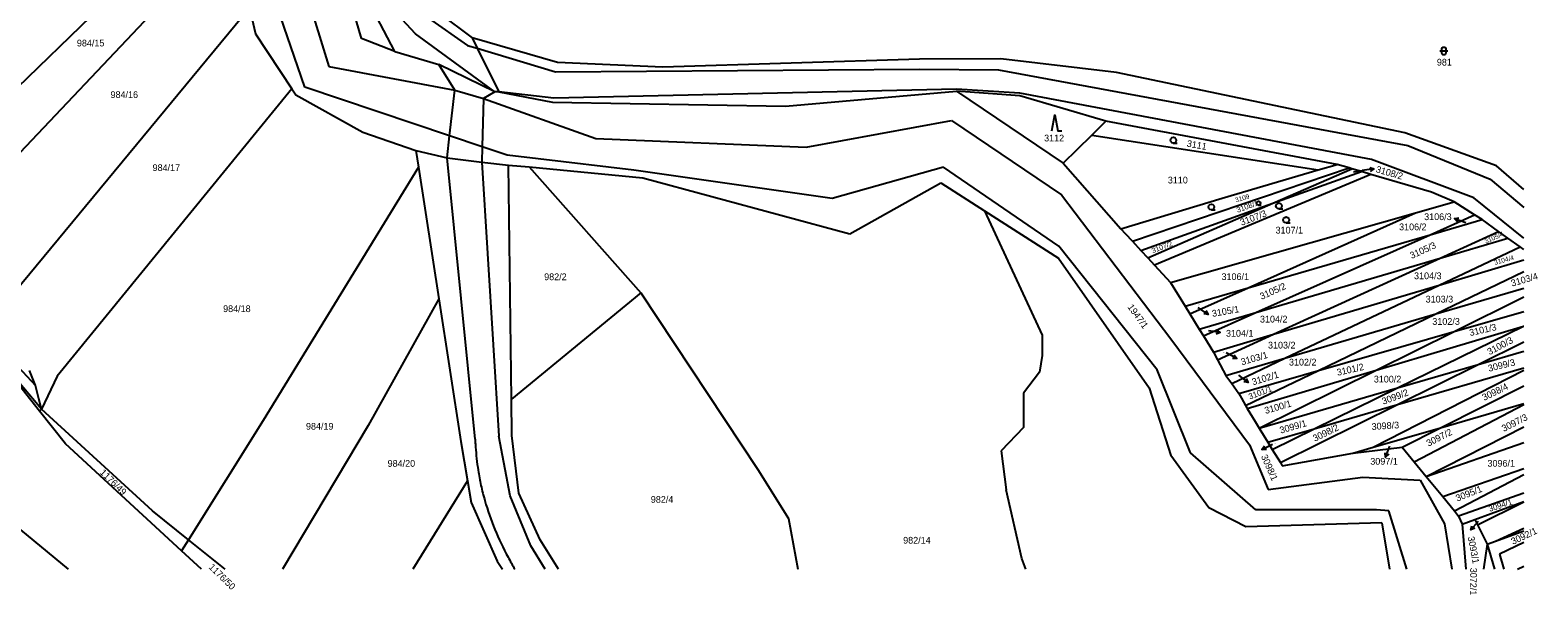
# Model space of a CAD drawing. Extents: x -621797 to -620972, y -1175539 to -1174697.
# Drawn here: x -621354.5 to -620973.6, y -1175539.3 to -1175396.7 of the extents above; entities that cross this region are included whole.
import ezdxf

# ---------------------------------------------------------------- set-up
doc = ezdxf.new("R2010")
doc.units = 0
for name, color, linetype in [('INZ mimo EON - nadz', 7, 'Continuous'), ('SDEL EON', 7, 'Continuous'), ('SDEL EON - popis', 7, 'Continuous'), ('Silnoproud EON', 7, 'Continuous'), ('Silnoproud EON - popis', 7, 'Continuous')]:
    doc.layers.add(name, color=color, linetype=linetype)

msp = doc.modelspace()

# ---------------------------------------------------------------- linework, layer by layer
at = {"layer": 'INZ mimo EON - nadz'}
for p, q in [((-621020.18, -1175432.47), (-621017.97, -1175432.16)), ((-621014.999, -1175431.743), (-621017.97, -1175432.16)), ((-620994.629, -1175444.275), (-620991.81, -1175445.3)), ((-621056.902, -1175468.48), (-621059.36, -1175466.76)), ((-621053.829, -1175473.097), (-621056.8, -1175472.68)), ((-621049.627, -1175479.602), (-621052.3, -1175478.24)), ((-621046.743, -1175485.685), (-621049.14, -1175483.88)), ((-621043.283, -1175502.592), (-621040.61, -1175501.23)), ((-621012.085, -1175504.531), (-621011.01, -1175501.73)), ((-620990.518, -1175522.934), (-620988.55, -1175520.67))]:
    msp.add_line(p, q, dxfattribs=at)
for points in [[(-621016.059, -1175431.387), (-621014.999, -1175431.743), (-621015.92, -1175432.377)], [(-620993.86, -1175445.086), (-620994.629, -1175444.275), (-620993.519, -1175444.147)], [(-621057.435, -1175467.497), (-621056.902, -1175468.48), (-621058.008, -1175468.316)], [(-621054.75, -1175472.463), (-621053.829, -1175473.097), (-621054.889, -1175473.453)], [(-621050.291, -1175478.703), (-621049.627, -1175479.602), (-621050.745, -1175479.594)], [(-621047.242, -1175484.684), (-621046.743, -1175485.685), (-621047.843, -1175485.482)], [(-621042.165, -1175502.583), (-621043.283, -1175502.592), (-621042.619, -1175501.692)], [(-621011.26, -1175503.776), (-621012.085, -1175504.531), (-621012.194, -1175503.418)], [(-620989.485, -1175522.507), (-620990.518, -1175522.934), (-620990.239, -1175521.851)]]:
    msp.add_lwpolyline(points, dxfattribs=at)
at = {"layer": 'SDEL EON'}
msp.add_lwpolyline([(-620997.82, -1175401.45), (-620997.72, -1175401.16), (-620997.47, -1175400.98), (-620997.16, -1175400.98), (-620996.91, -1175401.16), (-620996.81, -1175401.45), (-620996.81, -1175402.45), (-620996.91, -1175402.74), (-620997.16, -1175402.92), (-620997.47, -1175402.92), (-620997.72, -1175402.74), (-620997.82, -1175402.45)], close=True, dxfattribs=at)
for points in [[(-620998.32, -1175401.95), (-620997.05, -1175401.95), (-620996.32, -1175401.95)], [(-621096.38, -1175422.11), (-621095.63, -1175418.11), (-621094.88, -1175422.11), (-621093.88, -1175422.11)], [(-621065.66, -1175425.23), (-621066.04, -1175425.13), (-621066.31, -1175424.86), (-621066.41, -1175424.49), (-621066.31, -1175424.12), (-621066.04, -1175423.85), (-621065.67, -1175423.75), (-621065.3, -1175423.85), (-621065.03, -1175424.12), (-621064.93, -1175424.5), (-621065.03, -1175424.88), (-621065.3, -1175425.15), (-621065.68, -1175425.25), (-621064.68, -1175425.25)], [(-621056.05, -1175442.1), (-621056.43, -1175442), (-621056.7, -1175441.73), (-621056.8, -1175441.36), (-621056.7, -1175440.99), (-621056.43, -1175440.72), (-621056.06, -1175440.62), (-621055.69, -1175440.72), (-621055.42, -1175440.99), (-621055.32, -1175441.37), (-621055.42, -1175441.75), (-621055.69, -1175442.02), (-621056.07, -1175442.12), (-621055.07, -1175442.12)], [(-621044.13, -1175440.87), (-621044.385, -1175440.803), (-621044.566, -1175440.622), (-621044.632, -1175440.374), (-621044.566, -1175440.126), (-621044.385, -1175439.945), (-621044.137, -1175439.878), (-621043.889, -1175439.945), (-621043.708, -1175440.126), (-621043.641, -1175440.381), (-621043.708, -1175440.636), (-621043.889, -1175440.816), (-621044.143, -1175440.883), (-621043.473, -1175440.883)], [(-621038.99, -1175441.84), (-621039.37, -1175441.74), (-621039.64, -1175441.47), (-621039.74, -1175441.1), (-621039.64, -1175440.73), (-621039.37, -1175440.46), (-621039, -1175440.36), (-621038.63, -1175440.46), (-621038.36, -1175440.73), (-621038.26, -1175441.11), (-621038.36, -1175441.49), (-621038.63, -1175441.76), (-621039.01, -1175441.86), (-621038.01, -1175441.86)], [(-621037.16, -1175445.37), (-621037.54, -1175445.27), (-621037.81, -1175445), (-621037.91, -1175444.63), (-621037.81, -1175444.26), (-621037.54, -1175443.99), (-621037.17, -1175443.89), (-621036.8, -1175443.99), (-621036.53, -1175444.26), (-621036.43, -1175444.64), (-621036.53, -1175445.02), (-621036.8, -1175445.29), (-621037.18, -1175445.39), (-621036.18, -1175445.39)]]:
    msp.add_lwpolyline(points, dxfattribs=at)
at = {"layer": 'SDEL EON - popis'}
for p, q in [((-621292.93, -1175360.5), (-621279.04, -1175405.89)), ((-621285.12, -1175411.09), (-621299.97, -1175367.6)), ((-621257.16, -1175397.67), (-621270.32, -1175383.39)), ((-621253.83, -1175393.72), (-621243.98, -1175400.59)), ((-621237.07, -1175412.28), (-621257.16, -1175397.67)), ((-621243.98, -1175400.59), (-621241.51, -1175401.27)), ((-621241.51, -1175401.27), (-621221.72, -1175407.2)), ((-621247.23, -1175411.83), (-621251.26, -1175405.42)), ((-621279.04, -1175405.89), (-621247.23, -1175411.83)), ((-621221.72, -1175407.2), (-621129.8, -1175406.56)), ((-621129.8, -1175406.56), (-621109.82, -1175406.73)), ((-621109.82, -1175406.73), (-621006.47, -1175425.84)), ((-621248.5, -1175423.41), (-621285.12, -1175411.09)), ((-621248.5, -1175423.41), (-621247.23, -1175411.83)), ((-621247.23, -1175411.83), (-621239.98, -1175413.95)), ((-621237.07, -1175412.28), (-621239.98, -1175413.95)), ((-621222.14, -1175413.86), (-621236.04, -1175412.28)), ((-621120.48, -1175411.65), (-621222.14, -1175413.86)), ((-621104.47, -1175412.63), (-621120.48, -1175411.65)), ((-621015.6, -1175429.36), (-621104.47, -1175412.63)), ((-621239.98, -1175413.95), (-621240.29, -1175426.17)), ((-621239.98, -1175413.95), (-621211.57, -1175424.06)), ((-621158.44, -1175426.27), (-621121.73, -1175419.5)), ((-621121.73, -1175419.5), (-621093.92, -1175438.29)), ((-621249.11, -1175428.98), (-621248.5, -1175423.41)), ((-621240.29, -1175426.17), (-621248.5, -1175423.41)), ((-621211.57, -1175424.06), (-621158.44, -1175426.27)), ((-621240.29, -1175426.17), (-621240.39, -1175430.02)), ((-621233.98, -1175428.29), (-621240.29, -1175426.17)), ((-621226.14, -1175429.22), (-621233.98, -1175428.29)), ((-621006.47, -1175425.84), (-620985.63, -1175434.32)), ((-621242.06, -1175500.03), (-621249.11, -1175428.98)), ((-621240.39, -1175430.02), (-621236.06, -1175499.27)), ((-621201.98, -1175432.08), (-621226.14, -1175429.22)), ((-621151.88, -1175439.2), (-621201.98, -1175432.08)), ((-621123.75, -1175431.33), (-621151.88, -1175439.2)), ((-621094.57, -1175451.27), (-621123.75, -1175431.33)), ((-620989.75, -1175439.04), (-621015.6, -1175429.36)), ((-620985.63, -1175434.32), (-620977.15, -1175441.483)), ((-621093.92, -1175438.29), (-621066.32, -1175474.66)), ((-620977.15, -1175449.245), (-620989.75, -1175439.04)), ((-621069.73, -1175482.45), (-621094.57, -1175451.27)), ((-621066.32, -1175474.66), (-621046.47, -1175501.41)), ((-621061.34, -1175503.42), (-621069.73, -1175482.45)), ((-621233.25, -1175514.3), (-621236.06, -1175499.27)), ((-621044.82, -1175517.84), (-621061.34, -1175503.42)), ((-621046.47, -1175501.41), (-621041.73, -1175512.7)), ((-621041.73, -1175512.7), (-621017.8, -1175509.58)), ((-621017.8, -1175509.58), (-621003.35, -1175510.34)), ((-621003.35, -1175510.34), (-620997.17, -1175521.41)), ((-621228, -1175526.96), (-621233.25, -1175514.3)), ((-621014.32, -1175517.88), (-621044.82, -1175517.84)), ((-621011.23, -1175518.06), (-621014.32, -1175517.88)), ((-621006.711, -1175532.85), (-621011.23, -1175518.06)), ((-620997.17, -1175521.41), (-620995.336, -1175532.85)), ((-621224.335, -1175532.85), (-621228, -1175526.96))]:
    msp.add_line(p, q, dxfattribs=at)
msp.add_spline([(-621242.06, -1175500.03), (-621242.015, -1175501.006), (-621241.957, -1175501.981), (-621241.312, -1175507.81), (-621240.584, -1175511.677), (-621240.125, -1175513.605), (-621239.6, -1175515.53), (-621237.073, -1175522.835), (-621233.76, -1175529.78), (-621232.035, -1175532.85)], degree=3, dxfattribs=at)
at = {"layer": 'Silnoproud EON'}
for p, q in [((-621311.79, -1175366.75), (-621378.12, -1175430.97)), ((-621372.41, -1175443.7), (-621303.5, -1175371.14)), ((-621262.38, -1175402.07), (-621279.06, -1175370.17)), ((-621270.77, -1175398.82), (-621279.06, -1175370.17)), ((-621299.03, -1175391.16), (-621361.77, -1175466.98)), ((-621299.03, -1175391.16), (-621297.58, -1175397.66)), ((-621251.18, -1175392.43), (-621242.79, -1175398.69)), ((-621297.58, -1175397.66), (-621288.39, -1175411.55)), ((-621262.38, -1175402.07), (-621270.77, -1175398.82)), ((-621242.79, -1175398.69), (-621241.51, -1175401.27)), ((-621221.26, -1175404.9), (-621242.79, -1175398.69)), ((-621241.51, -1175401.27), (-621236.04, -1175412.28)), ((-621262.38, -1175402.07), (-621251.26, -1175405.42)), ((-621237.07, -1175412.28), (-621251.26, -1175405.42)), ((-621194.64, -1175406.06), (-621221.26, -1175404.9)), ((-621129.82, -1175404.05), (-621194.64, -1175406.06)), ((-621109.26, -1175403.95), (-621129.82, -1175404.05)), ((-621080.07, -1175407.37), (-621109.26, -1175403.95)), ((-621007.16, -1175422.62), (-621080.07, -1175407.37)), ((-621288.39, -1175411.55), (-621347.62, -1175484.1)), ((-621288.39, -1175411.55), (-621287.4, -1175413.04)), ((-621287.4, -1175413.04), (-621270.45, -1175422.49)), ((-621236.04, -1175412.28), (-621237.07, -1175412.28)), ((-621236.04, -1175412.28), (-621222.51, -1175414.93)), ((-621163.68, -1175415.92), (-621120.46, -1175412.13)), ((-621120.46, -1175412.13), (-621093.52, -1175430.33)), ((-621104.49, -1175413.32), (-621120.46, -1175412.13)), ((-621222.51, -1175414.93), (-621163.68, -1175415.92)), ((-621082.74, -1175419.72), (-621104.49, -1175413.32)), ((-621086.27, -1175423.2), (-621082.74, -1175419.72)), ((-621024.31, -1175430.61), (-621082.74, -1175419.72)), ((-621270.45, -1175422.49), (-621257.02, -1175427.11)), ((-621093.52, -1175430.33), (-621086.27, -1175423.2)), ((-621086.27, -1175423.2), (-621029.11, -1175432.02)), ((-620984.07, -1175431), (-621007.16, -1175422.62)), ((-621257.02, -1175427.11), (-621256.37, -1175431.29)), ((-621257.02, -1175427.11), (-621249.11, -1175428.98)), ((-621256.37, -1175431.29), (-621295.65, -1175495.27)), ((-621256.37, -1175431.29), (-621251.22, -1175464.6)), ((-621249.11, -1175428.98), (-621240.39, -1175430.02)), ((-621240.39, -1175430.02), (-621233.66, -1175430.77)), ((-621233.66, -1175430.77), (-621228.41, -1175431.26)), ((-621232.88, -1175489.88), (-621233.66, -1175430.77)), ((-621228.41, -1175431.26), (-621199.67, -1175434)), ((-621228.41, -1175431.26), (-621200.18, -1175463.05)), ((-621093.52, -1175430.33), (-621078.91, -1175446.89)), ((-621076.03, -1175449.99), (-621021.28, -1175431.5)), ((-621053.32, -1175439.13), (-621029.11, -1175432.02)), ((-621040.57, -1175440.44), (-621020.59, -1175431.71)), ((-621029.11, -1175432.02), (-621024.31, -1175430.61)), ((-621021.28, -1175431.5), (-621024.31, -1175430.61)), ((-621020.59, -1175431.71), (-621021.28, -1175431.5)), ((-621018.15, -1175432.43), (-621020.59, -1175431.71)), ((-620977.15, -1175436.942), (-620984.07, -1175431)), ((-621199.67, -1175434), (-621147.36, -1175448.12)), ((-621147.36, -1175448.12), (-621124.43, -1175435.27)), ((-621124.43, -1175435.27), (-621113.36, -1175442.35)), ((-621015.76, -1175433.13), (-621070.44, -1175456.05)), ((-621040.57, -1175440.44), (-621018.15, -1175432.43)), ((-621015.76, -1175433.13), (-621018.15, -1175432.43)), ((-621000.48, -1175437.64), (-621015.76, -1175433.13)), ((-621078.91, -1175446.89), (-621053.32, -1175439.13)), ((-620994.72, -1175440.09), (-621000.48, -1175437.64)), ((-621113.36, -1175442.35), (-621098.8, -1175473.7)), ((-621113.36, -1175442.35), (-621094.72, -1175454.27)), ((-621073.87, -1175452.34), (-621040.57, -1175440.44)), ((-621072.12, -1175454.23), (-621040.57, -1175440.44)), ((-621066.41, -1175460.4), (-621004.49, -1175442.86)), ((-621046.81, -1175461.77), (-621004.49, -1175442.86)), ((-621004.49, -1175442.86), (-620994.72, -1175440.09)), ((-621000.77, -1175448.37), (-620989.55, -1175443.37)), ((-620989.55, -1175443.37), (-620994.72, -1175440.09)), ((-620987.68, -1175444.56), (-620989.55, -1175443.37)), ((-621078.91, -1175446.89), (-621077.84, -1175448.04)), ((-621000.77, -1175448.37), (-620987.68, -1175444.56)), ((-620983.51, -1175447.54), (-620987.68, -1175444.56)), ((-621077.84, -1175448.04), (-621076.03, -1175449.99)), ((-621076.03, -1175449.99), (-621073.87, -1175452.34)), ((-621046.81, -1175461.77), (-621000.77, -1175448.37)), ((-621044.82, -1175467.98), (-621000.77, -1175448.37)), ((-620998.27, -1175454.28), (-620983.51, -1175447.54)), ((-620998.27, -1175454.28), (-620981.14, -1175449.24)), ((-620981.14, -1175449.24), (-620983.51, -1175447.54)), ((-620978.09, -1175451.42), (-620981.14, -1175449.24)), ((-621094.72, -1175454.27), (-621071.74, -1175487.03)), ((-621073.87, -1175452.34), (-621072.12, -1175454.23)), ((-621072.12, -1175454.23), (-621070.44, -1175456.05)), ((-621044.82, -1175467.98), (-620998.27, -1175454.28)), ((-621040.33, -1175473.48), (-620998.27, -1175454.28)), ((-620998.48, -1175461.08), (-620978.09, -1175451.42)), ((-620998.48, -1175461.08), (-620977.15, -1175454.753)), ((-620977.15, -1175452.09), (-620978.09, -1175451.42)), ((-621070.44, -1175456.05), (-621066.41, -1175460.4)), ((-620999.39, -1175468.39), (-620977.15, -1175457.682)), ((-621066.41, -1175460.4), (-621062.7, -1175466.39)), ((-621062.7, -1175466.39), (-621046.81, -1175461.77)), ((-621061.5, -1175468.33), (-621046.81, -1175461.77)), ((-621040.33, -1175473.48), (-620998.48, -1175461.08)), ((-621037.54, -1175479.58), (-620998.48, -1175461.08)), ((-620999.39, -1175468.39), (-620977.15, -1175461.867)), ((-621251.22, -1175464.6), (-621269.1, -1175496.56)), ((-621251.22, -1175464.6), (-621245.65, -1175500.57)), ((-621200.18, -1175463.05), (-621232.88, -1175489.88)), ((-621200.18, -1175463.05), (-621170.63, -1175507.7)), ((-621062.7, -1175466.39), (-621061.5, -1175468.33)), ((-620994.75, -1175472.8), (-620977.15, -1175464.072)), ((-621061.5, -1175468.33), (-621059.13, -1175472.19)), ((-621059.13, -1175472.19), (-621044.82, -1175467.98)), ((-621058.09, -1175473.88), (-621044.82, -1175467.98)), ((-621037.54, -1175479.58), (-620999.39, -1175468.39)), ((-621029.03, -1175482.66), (-620999.39, -1175468.39)), ((-620994.75, -1175472.8), (-620977.15, -1175467.74)), ((-621367.94, -1175470.72), (-621353.13, -1175486.42)), ((-621098.8, -1175473.7), (-621098.84, -1175478.9)), ((-621059.13, -1175472.19), (-621058.09, -1175473.88)), ((-621058.09, -1175473.88), (-621055.56, -1175478)), ((-621055.56, -1175478), (-621040.33, -1175473.48)), ((-621054.51, -1175479.96), (-621040.33, -1175473.48)), ((-621029.03, -1175482.66), (-620994.75, -1175472.8)), ((-621014.47, -1175482.58), (-620977.18, -1175471.5)), ((-621014.47, -1175482.58), (-620994.75, -1175472.8)), ((-621009.02, -1175487.07), (-620977.18, -1175471.5)), ((-620977.18, -1175471.5), (-620977.15, -1175471.485)), ((-620977.18, -1175471.5), (-620977.15, -1175471.491)), ((-621352.13, -1175492.89), (-621364.11, -1175477.82)), ((-621351.64, -1175492.41), (-621364.11, -1175477.82)), ((-620988.67, -1175481.16), (-620977.15, -1175475.45)), ((-620988.67, -1175481.16), (-620977.15, -1175477.811)), ((-621098.84, -1175478.9), (-621099.49, -1175483.12)), ((-621055.56, -1175478), (-621054.51, -1175479.96)), ((-621054.51, -1175479.96), (-621052.37, -1175483.93)), ((-621052.37, -1175483.93), (-621037.54, -1175479.58)), ((-621050.91, -1175485.96), (-621037.54, -1175479.58)), ((-621009.02, -1175491.24), (-620988.67, -1175481.16)), ((-621009.02, -1175487.07), (-620988.67, -1175481.16)), ((-621353.13, -1175486.42), (-621354.66, -1175482.66)), ((-621347.62, -1175484.1), (-621351.64, -1175492.41)), ((-621099.49, -1175483.12), (-621103.51, -1175488.42)), ((-621052.37, -1175483.93), (-621050.91, -1175485.96)), ((-621049.14, -1175488.44), (-621029.03, -1175482.66)), ((-621047.46, -1175491.53), (-621029.03, -1175482.66)), ((-621047.06, -1175492.27), (-621014.47, -1175482.58)), ((-621044, -1175497.23), (-621014.47, -1175482.58)), ((-621015.16, -1175502.05), (-620977.15, -1175482.614)), ((-621009.02, -1175491.24), (-620977.15, -1175481.962)), ((-621352.29, -1175489.81), (-621353.13, -1175486.42)), ((-621103.51, -1175488.42), (-621103.56, -1175497.02)), ((-621071.74, -1175487.03), (-621066.3, -1175504.09)), ((-621050.91, -1175485.96), (-621049.14, -1175488.44)), ((-621049.14, -1175488.44), (-621048.48, -1175489.65)), ((-621044, -1175497.23), (-621009.02, -1175487.07)), ((-621030.11, -1175497.38), (-621009.02, -1175487.07)), ((-620998.16, -1175497.1), (-620977.15, -1175486.501)), ((-621351.64, -1175492.41), (-621352.29, -1175489.81)), ((-621351.64, -1175492.41), (-621352.13, -1175492.89)), ((-621345.57, -1175501.14), (-621352.13, -1175492.89)), ((-621323.56, -1175518.1), (-621351.64, -1175492.41)), ((-621232.77, -1175499.04), (-621232.88, -1175489.88)), ((-621048.48, -1175489.65), (-621047.46, -1175491.53)), ((-621047.46, -1175491.53), (-621047.06, -1175492.27)), ((-621047.06, -1175492.27), (-621045.03, -1175495.56)), ((-621038.64, -1175505.91), (-621009.02, -1175491.24)), ((-621030.11, -1175497.38), (-621009.02, -1175491.24)), ((-621004.81, -1175505.74), (-620977.15, -1175491.209)), ((-620998.16, -1175497.1), (-620977.15, -1175490.986)), ((-621295.65, -1175495.27), (-621314.46, -1175525.4)), ((-621269.1, -1175496.56), (-621290.741, -1175532.85)), ((-621045.03, -1175495.56), (-621044, -1175497.23)), ((-621001.79, -1175509.45), (-620977.15, -1175496.854)), ((-621245.65, -1175500.57), (-621244, -1175510.49)), ((-621231.03, -1175513.63), (-621232.77, -1175499.04)), ((-621103.56, -1175497.02), (-621109.21, -1175502.95)), ((-621044, -1175497.23), (-621041.83, -1175500.79)), ((-621041.83, -1175500.79), (-621030.11, -1175497.38)), ((-621040.72, -1175502.57), (-621030.11, -1175497.38)), ((-621015.16, -1175502.05), (-620998.16, -1175497.1)), ((-621007.86, -1175501.99), (-620998.16, -1175497.1)), ((-621316.21, -1175528.2), (-621345.57, -1175501.14)), ((-621109.21, -1175502.95), (-621107.91, -1175512.83)), ((-621056.7, -1175517.38), (-621066.3, -1175504.09)), ((-621041.83, -1175500.79), (-621040.72, -1175502.57)), ((-621040.72, -1175502.57), (-621038.64, -1175505.91)), ((-621038.14, -1175506.71), (-621020.33, -1175503.55)), ((-621020.33, -1175503.55), (-621007.86, -1175501.99)), ((-621020.33, -1175503.55), (-621015.16, -1175502.05)), ((-621007.86, -1175501.99), (-621004.81, -1175505.74)), ((-621001.79, -1175509.45), (-620977.15, -1175500.83)), ((-621170.63, -1175507.7), (-621162.86, -1175520.01)), ((-621038.64, -1175505.91), (-621038.14, -1175506.71)), ((-621004.81, -1175505.74), (-621001.79, -1175509.45)), ((-620997.59, -1175514.48), (-620977.15, -1175507.434)), ((-621244, -1175510.49), (-621257.801, -1175532.85)), ((-621244, -1175510.49), (-621243.08, -1175516.03)), ((-621001.79, -1175509.45), (-620997.59, -1175514.48)), ((-620994.68, -1175518.1), (-620977.15, -1175508.886)), ((-621225.62, -1175525.43), (-621231.03, -1175513.63)), ((-621103.94, -1175530.11), (-621107.91, -1175512.83)), ((-620997.59, -1175514.48), (-620994.68, -1175518.1)), ((-620977.15, -1175513.628), (-620993.61, -1175519.43)), ((-620989.47, -1175520.26), (-620977.15, -1175515.747)), ((-620988.82, -1175521.61), (-620977.15, -1175515.804)), ((-621362.27, -1175518.54), (-621344.886, -1175532.85)), ((-621314.46, -1175525.4), (-621323.56, -1175518.1)), ((-621243.08, -1175516.03), (-621236.5, -1175530.8)), ((-621047.39, -1175522.13), (-621056.7, -1175517.38)), ((-620994.68, -1175518.1), (-620993.61, -1175519.43)), ((-620993.61, -1175519.43), (-620992.72, -1175521.47)), ((-621162.86, -1175520.01), (-621160.579, -1175532.85)), ((-621012.96, -1175521.1), (-621047.39, -1175522.13)), ((-621012.96, -1175521.1), (-621011.068, -1175532.85)), ((-620992.72, -1175521.47), (-620989.47, -1175520.26)), ((-620992.72, -1175521.47), (-620991.746, -1175532.85)), ((-620989.47, -1175520.26), (-620988.82, -1175521.61)), ((-620988.82, -1175521.61), (-620986.43, -1175526.55)), ((-620984.27, -1175525.75), (-620977.15, -1175522.444)), ((-620984.27, -1175525.75), (-620977.15, -1175523.114)), ((-621314.46, -1175525.4), (-621316.21, -1175528.2)), ((-621305.172, -1175532.85), (-621314.46, -1175525.4)), ((-621221.01, -1175532.85), (-621225.62, -1175525.43)), ((-620986.43, -1175526.55), (-620987.349, -1175532.85)), ((-620986.43, -1175526.55), (-620984.27, -1175525.75)), ((-620986.43, -1175526.55), (-620984.539, -1175532.85)), ((-620977.15, -1175526.062), (-620983.29, -1175529.03)), ((-621311.164, -1175532.85), (-621316.21, -1175528.2)), ((-621236.5, -1175530.8), (-621235.191, -1175532.85)), ((-621102.921, -1175532.85), (-621103.94, -1175530.11)), ((-620983.29, -1175529.03), (-620982.146, -1175532.85)), ((-620978.704, -1175532.85), (-620977.15, -1175532.077))]:
    msp.add_line(p, q, dxfattribs=at)

# ---------------------------------------------------------------- texts
at = {"layer": 'INZ mimo EON - nadz'}
for s, rotation, p in [('3108/2', 344.00386, (-621014.64, -1175432.57)), ('1947/1', 306.01676, (-621077.339, -1175466.648)), ('3105/1', 10.02676, (-621055.766, -1175469.139)), ('3103/1', 15.98552, (-621048.352, -1175481.355)), ('3102/1', 17.01685, (-621045.533, -1175486.421)), ('3098/1', 293.98464, (-621043.573, -1175504.337)), ('3093/1', 280.9785, (-620991.325, -1175524.733))]:
    msp.add_text(s, height=1.7, rotation=rotation, dxfattribs=at).set_placement(p)
for s, p in [('3106/3', (-621002.313, -1175444.68)), ('3104/1', (-621052.383, -1175474.11)), ('3097/1', (-621015.913, -1175506.45))]:
    msp.add_text(s, height=1.7, dxfattribs=at).set_placement(p)
at = {"layer": 'Silnoproud EON - popis'}
for s, height, p in [('984/15', 1.7, (-621342.673, -1175400.82)), ('981', 1.7, (-620999.103, -1175405.65)), ('984/16', 1.7, (-621334.173, -1175413.85)), ('3112', 1.7, (-621098.323, -1175424.81)), ('984/17', 1.7, (-621323.553, -1175432.29)), ('3110', 1.7, (-621067.073, -1175435.43)), ('3107/1', 1.7, (-621039.853, -1175448.07)), ('3106/2', 1.7, (-621008.643, -1175447.24)), ('3106/3', 0.1, (-620992.886, -1175445.19)), ('982/2', 1.7, (-621224.623, -1175459.85)), ('3106/1', 1.7, (-621053.503, -1175459.81)), ('3104/3', 1.7, (-621004.863, -1175459.6)), ('984/18', 1.7, (-621305.733, -1175467.91)), ('3103/3', 1.7, (-621001.943, -1175465.49)), ('3104/2', 1.7, (-621043.793, -1175470.54)), ('3102/3', 1.7, (-621000.253, -1175471.13)), ('3104/1', 0.1, (-621056.846, -1175472.17)), ('3103/2', 1.7, (-621041.763, -1175477.11)), ('3103/1', 0.1, (-621053.036, -1175478.13)), ('3102/2', 1.7, (-621036.463, -1175481.4)), ('3102/1', 0.1, (-621049.656, -1175484.33)), ('3100/2', 1.7, (-621015.033, -1175485.69)), ('984/19', 1.7, (-621284.803, -1175497.6)), ('3098/1', 0.1, (-621040.066, -1175501.11)), ('3097/1', 0.1, (-621010.706, -1175501.48)), ('984/20', 1.7, (-621264.173, -1175506.98)), ('3096/1', 1.7, (-620986.313, -1175506.95)), ('982/4', 1.7, (-621197.683, -1175516.07)), ('3093/1', 0.1, (-620988.956, -1175520.36)), ('982/14', 1.7, (-621133.933, -1175526.38))]:
    msp.add_text(s, height=height, dxfattribs=at).set_placement(p)
for s, height, rotation, p in [('3111', 1.7, 350.07721, (-621062.376, -1175426.111)), ('3108/2', 0.1, 19.82434, (-621020.167, -1175432.465)), ('3109', 1.2, 16.21471, (-621049.879, -1175440.233)), ('3108/1', 1.4, 19.82434, (-621049.436, -1175442.834)), ('3107/3', 1.7, 20.68378, (-621048.428, -1175446.126)), ('3107/2', 1.3, 20.68378, (-621070.87, -1175453.066)), ('3105/3', 1.7, 24.29341, (-621005.464, -1175454.512)), ('3105/4', 1.2, 24.29341, (-620986.707, -1175450.671)), ('3104/4', 1.2, 15.29797, (-620984.428, -1175455.996)), ('3103/4', 1.7, 16.21471, (-620980.092, -1175461.494)), ('3105/2', 1.7, 24.29341, (-621043.374, -1175464.832)), ('3105/1', 0.1, 26.12688, (-621059.407, -1175466.224)), ('3101/3', 1.7, 12.60507, (-620990.688, -1175473.968)), ('3100/3', 1.7, 27.90304, (-620985.81, -1175478.809)), ('3101/2', 1.7, 12.60507, (-621024.188, -1175484.008)), ('3099/3', 1.7, 13.5218, (-620985.949, -1175482.974)), ('3101/1', 1.5, 20.68378, (-621046.334, -1175490.016)), ('3099/2', 1.7, 20.68378, (-621012.608, -1175491.326)), ('3098/4', 1.7, 26.12688, (-620987.157, -1175490.355)), ('3100/1', 1.7, 16.21471, (-621042.372, -1175493.654)), ('3099/1', 1.7, 16.21471, (-621038.532, -1175498.624)), ('3098/2', 1.7, 26.12688, (-621029.937, -1175500.685)), ('3098/3', 1.7, 3.60963, (-621015.533, -1175497.685)), ('3097/3', 1.7, 26.98631, (-620982.188, -1175498.182)), ('3097/2', 1.7, 26.98631, (-621001.218, -1175501.912)), ('1176/49', 1.7, 315.87163, (-621337.008, -1175508.583)), ('3095/1', 1.7, 21.60051, (-620993.949, -1175515.783)), ('3094/1', 1.5, 17.99087, (-620985.731, -1175518.365)), ('3092/1', 1.7, 25.21014, (-620979.875, -1175526.699)), ('1176/50', 1.7, 315.87163, (-621309.508, -1175532.483)), ('3072/1', 1.7, 269.11828, (-620990.664, -1175532.467))]:
    msp.add_text(s, height=height, rotation=rotation, dxfattribs=at).set_placement(p)

doc.saveas('drawing.dxf')
